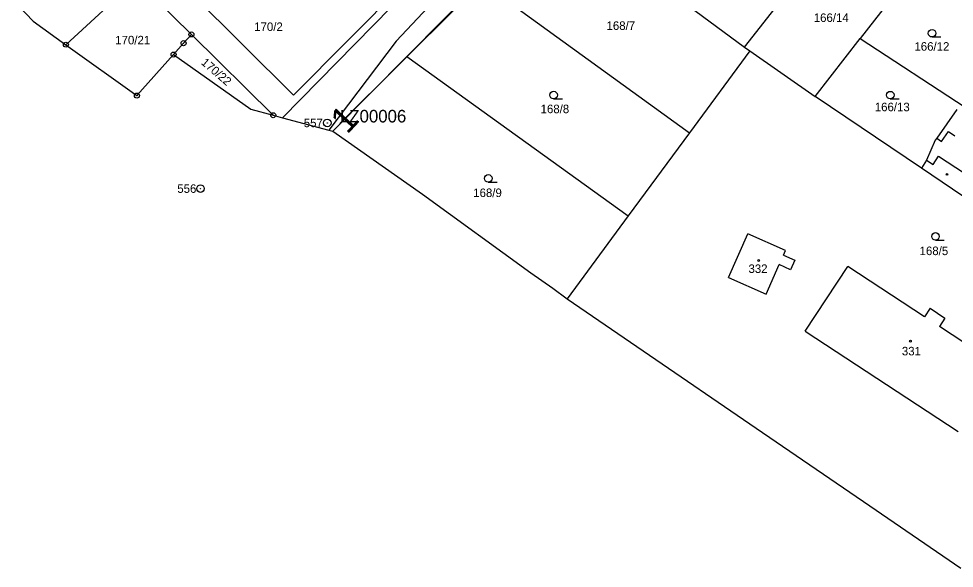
# Model space of a CAD drawing. Extents: x -738131 to -734179, y -1033447 to -1030078.
# Drawn here: x -736517 to -736330.8, y -1032648.6 to -1032539.2 of the extents above; entities that cross this region are included whole.
import ezdxf

# ---------------------------------------------------------------- set-up
doc = ezdxf.new("R2010")
doc.units = 0
for name, color, linetype in [('ftf_2050', 7, 'Continuous'), ('ftf_3010', 7, 'Continuous'), ('ftf_3010_ftf_3010_gtda_3015_gtda_3015_1', 7, 'Continuous'), ('Vrstva 1', 7, 'Continuous'), ('Vrstva 2', 7, 'Continuous'), ('Vrstva 3', 7, 'Continuous'), ('Vrstva 4', 7, 'Continuous'), ('Vrstva 5', 7, 'Continuous'), ('Vrstva 8', 7, 'Continuous')]:
    doc.layers.add(name, color=color, linetype=linetype)

msp = doc.modelspace()

# ---------------------------------------------------------------- linework, layer by layer
at = {"layer": 'ftf_2050'}
msp.add_lwpolyline([(-736453.1, -1032560.11), (-736417.28, -1032524.35)], dxfattribs=at)
at = {"layer": 'Vrstva 1'}
for points in [[(-736417.58, -1032511.12), (-736464.48, -1032558.93)], [(-736414.12, -1032514.16), (-736441.89, -1032543.72)], [(-736410.33, -1032516.96), (-736372.53, -1032544.91)], [(-736493.65, -1032531.49), (-736507.63, -1032544.39)], [(-736482.64, -1032542.36), (-736493.65, -1032531.49)], [(-736462.34, -1032554.47), (-736440.57, -1032532.49)], [(-736425.04, -1032531.84), (-736439.76, -1032546.73)], [(-736425.04, -1032531.84), (-736383.51, -1032561.93)], [(-736340.98, -1032532.14), (-736349.51, -1032543.13)], [(-736482.51, -1032534.36), (-736462.34, -1032554.47)], [(-736372.53, -1032544.91), (-736363.52, -1032533.37)], [(-736517.02, -1032536.72), (-736514.14, -1032539.73)], [(-736514.14, -1032539.73), (-736507.63, -1032544.39)], [(-736482.64, -1032542.36), (-736484.19, -1032544.09)], [(-736466.36, -1032558.43), (-736482.64, -1032542.36)], [(-736484.19, -1032544.09), (-736486.18, -1032546.35)], [(-736441.89, -1032543.72), (-736455.28, -1032561.4)], [(-736358.48, -1032554.68), (-736349.51, -1032543.13)], [(-736349.51, -1032543.13), (-736328.63, -1032556.84)], [(-736507.63, -1032544.39), (-736493.49, -1032554.52)], [(-736371.5, -1032545.63), (-736383.51, -1032561.93)], [(-736372.53, -1032544.91), (-736371.5, -1032545.63)], [(-736371.5, -1032545.63), (-736358.48, -1032554.68)], [(-736493.49, -1032554.52), (-736486.18, -1032546.35)], [(-736486.18, -1032546.35), (-736470.84, -1032557.23)], [(-736439.76, -1032546.73), (-736454.48, -1032561.62)], [(-736439.76, -1032546.73), (-736395.7, -1032578.47)], [(-736337.34, -1032568.95), (-736358.48, -1032554.68)], [(-736470.84, -1032557.23), (-736466.36, -1032558.43)], [(-736330.29, -1032557.31), (-736334.28, -1032562.98)], [(-736466.36, -1032558.43), (-736464.48, -1032558.93)], [(-736464.48, -1032558.93), (-736455.28, -1032561.4)], [(-736455.28, -1032561.4), (-736454.48, -1032561.62)], [(-736454.48, -1032561.62), (-736436.67, -1032574.17)], [(-736383.51, -1032561.93), (-736395.7, -1032578.47)], [(-736334.58, -1032563.4), (-736336.31, -1032567.37)], [(-736334.28, -1032562.98), (-736334.58, -1032563.4)], [(-736336.31, -1032567.37), (-736337.34, -1032568.95)], [(-736327.02, -1032575.91), (-736337.34, -1032568.95)], [(-736436.67, -1032574.17), (-736415.05, -1032589.79)], [(-736395.7, -1032578.47), (-736407.85, -1032594.95)], [(-736375.75, -1032590.72), (-736371.9, -1032582.01)], [(-736364.39, -1032585.34), (-736371.9, -1032582.01)], [(-736364.8, -1032586.26), (-736364.39, -1032585.34)], [(-736364.8, -1032586.26), (-736362.52, -1032587.27)], [(-736368.25, -1032594.04), (-736365.65, -1032588.18)], [(-736363.37, -1032589.19), (-736365.65, -1032588.18)], [(-736362.52, -1032587.27), (-736363.37, -1032589.19)], [(-736360.45, -1032601.45), (-736351.98, -1032588.54)], [(-736336.72, -1032598.54), (-736351.98, -1032588.54)], [(-736415.05, -1032589.79), (-736410.71, -1032592.88)], [(-736375.75, -1032590.72), (-736368.25, -1032594.04)], [(-736410.71, -1032592.88), (-736407.85, -1032594.95)], [(-736407.85, -1032594.95), (-736392.74, -1032605.3)], [(-736335.62, -1032596.86), (-736336.72, -1032598.54)], [(-736335.62, -1032596.86), (-736332.64, -1032598.81)], [(-736332.64, -1032598.81), (-736333.74, -1032600.49)], [(-736360.45, -1032601.45), (-736330.01, -1032621.41)], [(-736321.54, -1032608.5), (-736333.74, -1032600.49)], [(-736392.74, -1032605.3), (-736370.21, -1032620.72)], [(-736370.21, -1032620.72), (-736347.6, -1032636.21)], [(-736347.6, -1032636.21), (-736329.47, -1032648.62)]]:
    msp.add_lwpolyline(points, dxfattribs=at)
at = {"layer": 'Vrstva 3'}
for p, q in [((-736335.21, -1032542.86), (-736333.46, -1032542.86)), ((-736410.54, -1032555.16), (-736408.79, -1032555.16)), ((-736343.52, -1032555.18), (-736341.77, -1032555.18)), ((-736423.54, -1032571.75), (-736421.79, -1032571.75)), ((-736334.53, -1032583.31), (-736332.78, -1032583.31))]:
    msp.add_line(p, q, dxfattribs=at)
for centre in [(-736335.21, -1032542.11), (-736410.54, -1032554.41), (-736343.52, -1032554.43), (-736423.54, -1032571), (-736334.53, -1032582.56)]:
    msp.add_circle(centre, 0.75, dxfattribs=at)
at = {"layer": 'Vrstva 4'}
for points in [[(-736333.35, -1032563.63), (-736331.95, -1032561.65)], [(-736331.95, -1032561.65), (-736330.68, -1032562.54)], [(-736334.28, -1032562.98), (-736333.35, -1032563.63)], [(-736334.99, -1032568.23), (-736333.93, -1032566.6)], [(-736333.93, -1032566.6), (-736328.75, -1032569.97)], [(-736336.31, -1032567.37), (-736334.99, -1032568.23)]]:
    msp.add_lwpolyline(points, dxfattribs=at)
at = {"layer": 'Vrstva 5'}
for centre in [(-736332.23, -1032570.21), (-736369.72, -1032587.35), (-736339.52, -1032603.41)]:
    msp.add_circle(centre, 0.175, dxfattribs=at)
at = {"layer": 'Vrstva 8'}
for centre, radius in [((-736482.64, -1032542.36), 0.5), ((-736482.64, -1032542.36), 0.0303), ((-736507.63, -1032544.39), 0.5), ((-736484.19, -1032544.09), 0.5), ((-736484.19, -1032544.09), 0.0303), ((-736507.63, -1032544.39), 0.0303), ((-736486.18, -1032546.35), 0.5), ((-736486.18, -1032546.35), 0.0303), ((-736493.49, -1032554.52), 0.5), ((-736493.49, -1032554.52), 0.0303), ((-736466.36, -1032558.43), 0.5), ((-736466.36, -1032558.43), 0.0303), ((-736455.59, -1032559.96), 0.75), ((-736455.59, -1032559.96), 0.03), ((-736480.83, -1032573.04), 0.75), ((-736480.83, -1032573.04), 0.03)]:
    msp.add_circle(centre, radius, dxfattribs=at)

# ---------------------------------------------------------------- texts
at = {"layer": 'ftf_3010'}
msp.add_text('1', height=5.2, rotation=47.1055, dxfattribs=at).set_placement((-736451.64, -1032562.36))
at = {"layer": 'ftf_3010_ftf_3010_gtda_3015_gtda_3015_1'}
msp.add_text('LZ00006', height=2.5, dxfattribs=at).set_placement((-736453.07, -1032559.87))
at = {"layer": 'Vrstva 2'}
for s, p in [('166/14', (-736358.76, -1032539.87)), ('170/2', (-736470.14, -1032541.67)), ('168/7', (-736400.01, -1032541.45)), ('170/21', (-736497.8, -1032544.33)), ('166/12', (-736338.72, -1032545.59)), ('168/8', (-736413.13, -1032558.03)), ('166/13', (-736346.61, -1032557.64)), ('168/9', (-736426.54, -1032574.72)), ('168/5', (-736337.69, -1032586.28)), ('332', (-736371.75, -1032589.83)), ('331', (-736341.22, -1032606.24))]:
    msp.add_text(s, height=1.7, dxfattribs=at).set_placement(p)
msp.add_text('170/22', height=1.7, rotation=319.1666, dxfattribs=at).set_placement((-736480.85, -1032548.14))
at = {"layer": 'Vrstva 8'}
for s, p in [('557', (-736460.28, -1032560.81)), ('556', (-736485.45, -1032573.89))]:
    msp.add_text(s, height=1.7, dxfattribs=at).set_placement(p)

doc.saveas('drawing.dxf')
